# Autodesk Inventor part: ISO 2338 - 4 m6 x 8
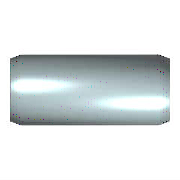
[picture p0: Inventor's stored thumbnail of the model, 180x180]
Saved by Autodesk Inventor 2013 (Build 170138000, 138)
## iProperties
Created: 2012-02
Part Number: ISO 2338 - 4 m6 x 8
Material: Stainless Steel, Austenitic
Description: Parallel Pin
Document SubType Name: Modeling
Standard: ISO 2338
Designer: rYan
Standards Organization: DIN
Language: en-US
Size Designation: 4 m6 x 8
Categories: <MemberInstance><Categories><Category DisplayName="Fasteners" InternalName="e4da775c-781d-43d5-af7c-5136215cf5a6" Mnemonic="FSTN"><Category DisplayName="Pins" I
Density: 8.03 g/cm^3
IsCustomPart: 0
Author: rYan
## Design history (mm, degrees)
sketch "Sketch"
  geometry: C1 r 2 at (0, 0); 1 further point
  constraints: 1 centre point, 1 coincident
  dimensions: "d1" = 4 diameter of C1 (= NND)
extrude "Body" new body sketch "Sketch" distance "d2" = 8 (= NLG); taper "d3" = 0 deg
body "Solid1"
chamfer "Chamfer1" distance "d4" = 0.63 (= PHH); stored, may be unused: angle "d5" = 15 deg (= FAWI), second distance "d11" = 0.63 (= PHH)
chamfer "Chamfer2" distance "d8" = 0.63 (= PHH); stored, may be unused: angle "d9" = 15 deg (= FAWI), second distance "d12" = 0.63 (= PHH)
other parameters: "NND" = 4 [user parameter; used in 1 equation term], "NLG" = 8 [user parameter; used in 1 equation term], "PHH" = 0.63 [user parameter; used in 4 equation terms], "FAWI" = 15 deg [user parameter; used in 2 equation terms], "d13" = 0, "d15" = 0, "d16" = 0, "KAH" = 0 [user parameter]
